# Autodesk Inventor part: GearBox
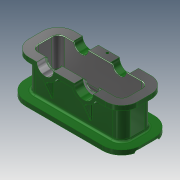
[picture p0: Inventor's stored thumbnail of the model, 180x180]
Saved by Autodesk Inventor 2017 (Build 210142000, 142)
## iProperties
Created: 2016-10
Part Number: GearBox
Material: Generic
Document SubType Name: Modeling
Designer: Drago Šandor
Density: 1 g/cm^3
Appearance: Smooth - Dark Forest Green
Author: Drago Šandor
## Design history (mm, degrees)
sketch "Sketch1"
  geometry: L1 (0, -147)-(0, 147) reference; L2 (-49, 0)-(49, 0) reference; L3 (35, 105)-(-35, 105); L4 (-35, 105)-(-35, -105); L5 (-35, -105)-(35, -105); L6 (35, -105)-(35, 105); 3 further points
  constraints: 8 end point, 2 midpoint, 2 parallel, 2 point on line, 1 horizontal, 1 perpendicular
  dimensions: "d0" = 70 distance of L4.end L5.end; "d1" = 210 distance of L5.end L3.start
extrude "Extrusion1" new body sketch "Sketch1" distance "d2" = 90; taper "d3" = 0 deg
fillet "Fillet1" dims "d4" = 20
shell "Shell1" dims "d5" = 6
fillet "Fillet2" dims "d6" = 20
sketch "Sketch2"
  geometry: L1 (-15, -105)-(15, -105) reference; L2 (-35, 85)-(-35, -85) reference; L3 (15, 105)-(-15, 105) reference; L4 (35, -85)-(35, 85) reference; L5 (-15, -127)-(15, -127); L6 (57, -85)-(57, 85); L7 (15, 127)-(-15, 127); L8 (-57, 85)-(-57, -85); A1 r 20 centre (-15, -85) between (-35, -85) and (-15, -105) reference; A2 r 20 centre (-15, 85) between (-15, 105) and (-35, 85) reference; A3 r 20 centre (15, 85) between (35, 85) and (15, 105) reference; A4 r 20 centre (15, -85) between (15, -105) and (35, -85) reference; A5 r 42 centre (-15, -85) between (-57, -85) and (-15, -127); A6 r 42 centre (15, -85) between (15, -127) and (57, -85); A7 r 42 centre (15, 85) between (57, 85) and (15, 127); A8 r 42 centre (-15, 85) between (-15, 127) and (-57, 85); 1 further point
  constraints: 8 end point, 8 point on circle, 4 centre point
  dimensions: "d7" = 22 distance between parallel lines of L2 L8
extrude "Extrusion2" join sketch "Sketch2" distance "d8" = 10; taper "d9" = 0 deg
sketch "Sketch3"
  geometry: L1 (35, -85)-(35, 85) reference; L2 (-15, -105)-(15, -105) reference; L3 (-35, 85)-(-35, -85) reference; L4 (15, 105)-(-15, 105) reference; L5 (15, 120)-(-15, 120); L6 (-50, 85)-(-50, -85); L7 (-15, -120)-(15, -120); L8 (50, -85)-(50, 85); A1 r 20 centre (15, 85) between (35, 85) and (15, 105) reference; A2 r 20 centre (15, -85) between (15, -105) and (35, -85) reference; A3 r 20 centre (-15, -85) between (-35, -85) and (-15, -105) reference; A4 r 20 centre (-15, 85) between (-15, 105) and (-35, 85) reference; A5 r 35 centre (15, 85) between (50, 85) and (15, 120); A6 r 35 centre (-15, 85) between (-15, 120) and (-50, 85); A7 r 35 centre (-15, -85) between (-50, -85) and (-15, -120); A8 r 35 centre (15, -85) between (15, -120) and (50, -85); 1 further point
  constraints: 8 end point, 8 point on circle, 4 centre point
  dimensions: "d10" = 15 distance between parallel lines of L1 L8
extrude "Extrusion3" join sketch "Sketch3" distance "d11" = 10; taper "d12" = 0 deg
sketch "Sketch4"
  geometry: L1 (30, 0)-(0, 0) reference; L2 (-12, 0)-(42, 0); L3 (42, 0)-(42, 5); L4 (42, 5)-(-12, 5); L5 (-12, 5)-(-12, 0); L6 (-42, 0)-(-42, 10) reference; L7 (72, 0)-(72, 10) reference; 1 further point
  constraints: 8 end point, 2 parallel, 1 horizontal, 1 perpendicular, 1 point on line
  dimensions: "d13" = 5 distance of L2.end L3.end; "d14" = 30 distance between parallel lines of L5 L6; "d15" = 30 distance between parallel lines of L7 L3
extrude "Extrusion4" cut sketch "Sketch4" stored distance "d16" = 10; taper "d17" = 0 deg
fillet "Fillet3" dims "d18" = 5
fillet "Fillet4" dims "d19" = 5
chamfer "Chamfer1" distance "d20" = 1; stored, may be unused: second distance "d21" = 2, angle "d22" = 45 deg
sketch "Sketch5"
  geometry: L1 (0, 0)-(170, 0) reference; L2 (184, -64)-(184, -1) reference; L3 (205, 0)-(170, 0) reference; L4 (170, -1)-(184, -1) reference; L5 (0, 0)-(170, 0) reference; L6 (21.5, 0)-(76.5, 0); L7 (106.5, 0)-(161.5, 0); A1 r 27.5 centre (49, 0) between (21.5, 0) and (76.5, 0); A2 r 27.5 centre (134, 0) between (106.5, 0) and (161.5, 0); 2 further points
  constraints: 6 point on line, 4 end point, 4 point on circle, 2 centre point, 2 collinear, 1 coincident
  dimensions: "d23" = 55 diameter of A1; "d24" = 55 diameter of A2; "d25" = 50 horizontal distance of A2.centre point (184, -1); "d26" = 85 distance of A1.centre A2.centre
extrude "Extrusion5" join sketch "Sketch5" stored distance "d27" = 10; taper "d28" = 0 deg
sketch "Sketch6"
  geometry: C1 r 17.5 at (49, 0); C2 r 18.5 at (134, 0); A1 r 27.5 centre (49, 0) between (23.383, -10) and (74.617, -10) reference; A2 r 27.5 centre (134, 0) between (108.383, -10) and (159.617, -10) reference; 1 further point
  constraints: 2 centre point, 2 coincident
  dimensions: "d29" = 35 diameter of C1; "d30" = 37 diameter of C2
extrude "Extrusion6" cut sketch "Sketch6" distance "d31" = 19; taper "d32" = 0 deg
sketch "Sketch7"
  geometry: L1 (34, 0)-(64, 0); L2 (0, 0)-(170, 0) reference; L3 (118, 0)-(150, 0); A1 r 17.5 centre (49, 0) between (31.5, 0) and (66.5, 0) reference; A2 r 18.5 centre (134, 0) between (115.5, 0) and (152.5, 0) reference; A3 r 15 centre (49, 0) between (34, 0) and (64, 0); A4 r 16 centre (134, 0) between (118, 0) and (150, 0); 1 further point
  constraints: 4 end point, 4 point on circle, 2 centre point, 2 collinear
  dimensions: "d33" = 2.5 radial gap between concentric circles of A1 A3; "d34" = 2.5 radial gap between concentric circles of A2 A4
extrude "Extrusion7" cut sketch "Sketch7" stored distance "d35" = 19; taper "d36" = 0 deg
workaxis "Work Axis1"
workaxis "Work Axis2"
workplane "Work Plane1"
workplane "Work Plane2"
sketch "Sketch8"
  geometry: L1 (0, 10)-(0, 27.5) reference; L2 (0, 27.5)-(0, 32.5); L3 (0, 27.5)-(15, 27.5) reference; L4 (15, 75)-(15, 10) reference; L5 (0, 32.5)-(15, 67.5); L6 (15, 27.5)-(15, 67.5); L7 (15, 10)-(15, 75) reference; L8 (15, 27.5)-(0, 27.5); 1 further point
  constraints: 8 end point, 2 collinear, 1 point on line, 1 vertical
  dimensions: "d39" = 5 distance of L1.end L2.end; "d40" = 35 vertical distance of L5.end L2.end
feature "Rib1" sketch "Sketch8" dims "d41" = 1, "d42" = 5, "d43" = 0, "d44" = 0, "d45" = 1, "d46" = 1
sketch "Sketch10"
  geometry: L1 (0, 27.5)-(15, 27.5) reference; L2 (15, 10)-(15, 75) reference; L3 (0, 27.5)-(0, 32.5); L4 (0, 32.5)-(15, 67.5); 1 further point
  constraints: 4 end point, 1 point on line, 1 vertical
  dimensions: "d47" = 5 distance of L1.start L3.end; "d48" = 35 vertical distance of L4.end L3.end
feature "Rib2" sketch "Sketch10" dims "d49" = 1, "d50" = 5, "d51" = 0, "d52" = 0, "d53" = 1, "d54" = 1
fillet "Fillet5" dims "d55" = 2
workplane "Work Plane3"
mirror "Mirror1"
fillet "Fillet6" dims "d56" = 5
fillet "Fillet7" dims "d57" = 2
sketch "Sketch11"
  geometry: L1 (150, 10)-(170, 10) reference; L2 (152.5, 10)-(151.5, 10); L3 (116.5, 10)-(115.5, 10); A1 r 18.5 centre (134, 10) between (115.5, 10) and (152.5, 10) reference; A2 r 17.5 centre (134, 10) between (116.5, 10) and (151.5, 10); A3 r 18.5 centre (134, 10) between (115.5, 10) and (152.5, 10); 2 further points
  constraints: 4 end point, 4 point on circle, 2 centre point, 2 coincident
  dimensions: "d58" = 35 diameter of A2
extrude "Extrusion8" join sketch "Sketch11" stored distance "d59" = 10; taper "d60" = 0 deg
sketch "Sketch12"
  geometry: C1 r 21 at (49, 10); A1 r 17.5 centre (49, 10) between (31.5, 10) and (66.5, 10) reference; 1 further point
  constraints: 1 centre point, 1 coincident
  dimensions: "d61" = 42 diameter of C1
extrude "Extrusion9" cut sketch "Sketch12" stored distance "d62" = 10; taper "d63" = 0 deg
mirror "Mirror2"
sketch "Sketch13"
  geometry: L1 (57, -85)-(57, 85) reference; L2 (40, 23.383)-(50, 23.383) reference; L3 (35.162, -36.5)-(50, -36.5) reference; L4 (50, -10.383)-(40, -10.383) reference; 2 further points
  dimensions: "d64" = 12 distance from line of L1 point (45, 6.617); "d68" = 17 distance from line of L4 point (45, 6.617)
hole "Hole1" sketch "Sketch13" at (45, 6.617) diameter "d69" = 5; stored, may be unused: countersink angle "d73" = 90 deg, drill point angle "d75" = 118 deg; dims "d70" = 6, "d71" = 4, "d72" = 2, "d74" = 8
body "Solid1"
other parameters: "d37" = 0, "d38" = 0
